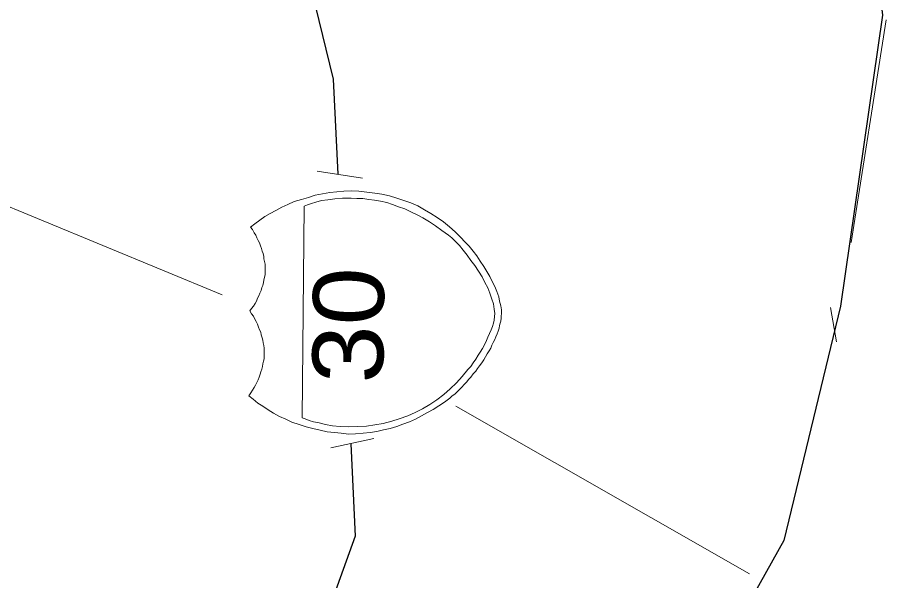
# Model space of a CAD drawing. Extents: x 2356576 to 2377878, y 6966390 to 6990634.
# Drawn here: x 2365920.6 to 2366004.5, y 6968831.6 to 6968885.6 of the extents above; entities that cross this region are included whole.
import ezdxf

# ---------------------------------------------------------------- set-up
doc = ezdxf.new("R2010")
doc.units = 0
doc.header["$LTSCALE"] = 7.1
doc.layers.add('19', color=7, linetype='Continuous', lineweight=13)
doc.layers.add('8', color=7, linetype='Continuous', lineweight=13)

msp = doc.modelspace()

# ---------------------------------------------------------------- linework, layer by layer
at = {"layer": '19'}
for p, q in [((2366003.959, 6968885.355), (2366000.59, 6968864.029)), ((2365949.354, 6968870.86), (2365953.728, 6968870.183)), ((2365999.2, 6968854.503), (2365998.633, 6968857.777)), ((2365962.654, 6968848.341), (2365990.84, 6968832.236)), ((2365950.672, 6968844.325), (2365954.789, 6968845.21))]:
    msp.add_line(p, q, dxfattribs=at)
at = {"layer": '19', "lineweight": 25}
for points in [[(2365993.212, 6969055.404), (2365995.144, 6969044.943), (2365996.174, 6969031.612), (2365997.392, 6969012.874), (2365997.254, 6968999.555), (2365998.323, 6968990.003), (2366002.006, 6968983.305), (2366004.476, 6968969.926), (2366002.874, 6968951.222), (2366001.496, 6968934.107), (2366000.162, 6968915.368), (2366003.604, 6968885.811), (2365999.567, 6968857.919), (2365994.142, 6968835.442), (2365986.716, 6968822.166), (2365969.062, 6968818.241), (2365951.423, 6968818.424), (2365942.698, 6968815.994), (2365930.315, 6968822.751)], [(2365935.418, 6968970.522), (2365940.314, 6968948.062), (2365943.664, 6968909.293), (2365950.886, 6968879.693), (2365951.331, 6968870.568)], [(2365952.596, 6968844.725), (2365953.012, 6968835.868), (2365949.152, 6968825.108), (2365948.988, 6968809.237), (2365953.546, 6968774.267)]]:
    msp.add_lwpolyline(points, dxfattribs=at)
at = {"layer": '19'}
for points in [[(2365898.594, 6968894.279), (2365917.316, 6968868.46), (2365940.231, 6968859.014)], [(2365943.525, 6968858.408), (2365943.648, 6968858.679), (2365943.77, 6968858.917), (2365943.865, 6968859.156), (2365943.988, 6968859.423), (2365944.05, 6968859.694), (2365944.141, 6968859.902), (2365944.203, 6968860.173), (2365944.238, 6968860.413), (2365944.301, 6968860.68), (2365944.363, 6968860.919), (2365944.366, 6968861.191), (2365944.369, 6968861.459), (2365944.371, 6968861.699), (2365944.374, 6968861.939), (2365944.316, 6968862.212), (2365944.259, 6968862.452), (2365944.229, 6968862.693), (2365944.172, 6968862.961), (2365944.087, 6968863.202), (2365944.029, 6968863.443), (2365943.912, 6968863.716), (2365943.823, 6968863.985), (2365943.705, 6968864.226), (2365943.588, 6968864.467), (2365943.47, 6968864.709), (2365943.325, 6968864.95), (2365943.148, 6968865.252), (2365942.97, 6968865.494), (2365943.394, 6968865.822), (2365943.846, 6968866.177), (2365944.329, 6968866.5), (2365944.844, 6968866.795), (2365945.387, 6968867.089), (2365945.958, 6968867.415), (2365946.561, 6968867.677), (2365947.164, 6968867.943), (2365947.858, 6968868.143), (2365948.52, 6968868.349), (2365949.182, 6968868.55), (2365949.872, 6968868.695), (2365950.565, 6968868.807), (2365951.254, 6968868.888), (2365951.915, 6968868.941), (2365952.635, 6968868.966), (2365953.355, 6968868.927), (2365954.134, 6968868.858), (2365954.885, 6968868.763), (2365955.572, 6968868.664), (2365956.29, 6968868.508), (2365957.008, 6968868.261), (2365957.666, 6968868.042), (2365958.355, 6968867.827), (2365959.012, 6968867.52), (2365959.668, 6968867.153), (2365960.265, 6968866.815), (2365960.889, 6968866.42), (2365961.485, 6968865.994), (2365962.052, 6968865.536), (2365962.615, 6968865.05), (2365963.149, 6968864.505), (2365963.537, 6968864.081), (2365963.953, 6968863.656), (2365964.336, 6968863.204), (2365964.691, 6968862.749), (2365965.018, 6968862.237), (2365965.341, 6968861.722), (2365965.636, 6968861.239), (2365965.931, 6968860.756), (2365966.166, 6968860.273), (2365966.401, 6968859.791), (2365966.608, 6968859.309), (2365966.782, 6968858.799), (2365966.866, 6968858.406), (2365966.982, 6968857.957), (2365967.038, 6968857.564), (2365967.066, 6968857.204)], [(2365967.066, 6968857.204), (2365967.031, 6968856.964), (2365967.029, 6968856.756), (2365966.998, 6968856.485), (2365966.936, 6968856.277), (2365966.874, 6968856.066), (2365966.811, 6968855.798), (2365966.716, 6968855.527), (2365966.626, 6968855.26), (2365966.503, 6968854.99), (2365966.408, 6968854.723), (2365966.257, 6968854.424), (2365966.135, 6968854.185), (2365966.011, 6968853.887), (2365965.857, 6968853.616), (2365965.674, 6968853.35), (2365965.523, 6968853.052), (2365965.34, 6968852.782), (2365965.157, 6968852.483), (2365964.942, 6968852.186), (2365964.759, 6968851.947), (2365964.576, 6968851.681), (2365964.334, 6968851.412), (2365964.123, 6968851.114), (2365963.908, 6968850.908), (2365963.698, 6968850.638), (2365963.483, 6968850.401), (2365963.24, 6968850.135), (2365963.03, 6968849.925), (2365962.788, 6968849.688), (2365962.574, 6968849.482), (2365962.332, 6968849.304), (2365962.09, 6968849.095), (2365961.578, 6968848.712), (2365961.034, 6968848.358), (2365960.49, 6968848.003), (2365959.947, 6968847.709), (2365959.372, 6968847.383), (2365958.801, 6968847.089), (2365958.226, 6968846.827), (2365957.595, 6968846.593), (2365957.021, 6968846.387), (2365956.359, 6968846.186), (2365955.73, 6968846.041), (2365955.096, 6968845.899), (2365954.435, 6968845.786), (2365953.774, 6968845.733), (2365953.054, 6968845.68), (2365952.393, 6968845.655), (2365951.674, 6968845.723), (2365951.015, 6968845.79), (2365950.327, 6968845.857), (2365949.637, 6968846.016), (2365948.951, 6968846.171), (2365948.292, 6968846.358), (2365947.635, 6968846.577), (2365946.945, 6968846.792), (2365946.348, 6968847.07), (2365945.751, 6968847.344), (2365945.186, 6968847.65), (2365944.649, 6968847.988), (2365944.141, 6968848.321), (2365943.664, 6968848.626), (2365943.219, 6968848.99), (2365942.803, 6968849.327), (2365942.986, 6968849.593), (2365943.169, 6968849.863), (2365943.319, 6968850.129), (2365943.441, 6968850.34), (2365943.564, 6968850.607), (2365943.687, 6968850.846), (2365943.782, 6968851.117), (2365943.904, 6968851.383), (2365943.967, 6968851.623), (2365944.057, 6968851.862), (2365944.12, 6968852.133), (2365944.155, 6968852.373), (2365944.217, 6968852.64), (2365944.28, 6968852.88), (2365944.282, 6968853.12), (2365944.285, 6968853.42), (2365944.288, 6968853.632), (2365944.29, 6968853.9), (2365944.233, 6968854.14), (2365944.176, 6968854.413), (2365944.146, 6968854.653), (2365944.089, 6968854.894), (2365944.003, 6968855.163), (2365943.946, 6968855.435), (2365943.828, 6968855.645), (2365943.739, 6968855.917), (2365943.622, 6968856.187), (2365943.505, 6968856.46), (2365943.387, 6968856.669), (2365943.242, 6968856.943), (2365943.064, 6968857.185), (2365942.887, 6968857.454), (2365943.07, 6968857.692), (2365943.252, 6968857.903), (2365943.403, 6968858.169), (2365943.525, 6968858.408)]]:
    msp.add_lwpolyline(points, dxfattribs=at)
msp.add_lwpolyline([(2365948.12, 6968867.513), (2365947.909, 6968847.202), (2365948.208, 6968847.111), (2365948.599, 6968846.955), (2365949.017, 6968846.83), (2365949.556, 6968846.737), (2365950.155, 6968846.578), (2365950.842, 6968846.451), (2365951.561, 6968846.384), (2365952.401, 6968846.347), (2365953.213, 6968846.367), (2365954.081, 6968846.418), (2365954.895, 6968846.529), (2365955.704, 6968846.673), (2365956.518, 6968846.873), (2365957.241, 6968847.105), (2365958.052, 6968847.397), (2365958.775, 6968847.721), (2365959.471, 6968848.074), (2365960.163, 6968848.487), (2365960.86, 6968848.928), (2365961.525, 6968849.433), (2365962.131, 6968849.995), (2365962.737, 6968850.56), (2365963.283, 6968851.183), (2365963.83, 6968851.837), (2365964.101, 6968852.134), (2365964.317, 6968852.492), (2365964.588, 6968852.821), (2365964.804, 6968853.207), (2365965.015, 6968853.505), (2365965.231, 6968853.863), (2365965.415, 6968854.221), (2365965.599, 6968854.611), (2365965.75, 6968854.937), (2365965.906, 6968855.296), (2365966.058, 6968855.654), (2365966.181, 6968855.953), (2365966.276, 6968856.284), (2365966.339, 6968856.583), (2365966.371, 6968856.911), (2365966.406, 6968857.211), (2365966.35, 6968857.631), (2365966.296, 6968858.144), (2365966.12, 6968858.594), (2365965.946, 6968859.168), (2365965.739, 6968859.678), (2365965.445, 6968860.193), (2365965.182, 6968860.736), (2365964.856, 6968861.279), (2365964.502, 6968861.823), (2365964.119, 6968862.307), (2365963.764, 6968862.79), (2365963.377, 6968863.274), (2365963.021, 6968863.726), (2365962.665, 6968864.09), (2365962.281, 6968864.454), (2365961.952, 6968864.729), (2365961.328, 6968865.184), (2365960.733, 6968865.61), (2365960.137, 6968866.008), (2365959.508, 6968866.375), (2365958.944, 6968866.681), (2365958.346, 6968866.955), (2365957.777, 6968867.233), (2365957.179, 6968867.447), (2365956.582, 6968867.665), (2365956.044, 6968867.851), (2365955.445, 6968867.977), (2365954.878, 6968868.071), (2365954.306, 6968868.137), (2365953.739, 6968868.235), (2365953.167, 6968868.24), (2365952.628, 6968868.274), (2365951.787, 6968868.255), (2365951.067, 6968868.202), (2365950.378, 6968868.117), (2365949.777, 6968868.036), (2365949.236, 6968867.889), (2365948.814, 6968867.746), (2365948.421, 6968867.63)], close=True, dxfattribs=at)
at = {"layer": '8'}
for p, q in [((2366003.959, 6968885.355), (2366000.59, 6968864.029)), ((2365949.354, 6968870.86), (2365953.728, 6968870.183)), ((2365999.2, 6968854.503), (2365998.633, 6968857.777)), ((2365962.654, 6968848.341), (2365990.84, 6968832.236)), ((2365950.672, 6968844.325), (2365954.789, 6968845.21))]:
    msp.add_line(p, q, dxfattribs=at)
at = {"layer": '8', "lineweight": 25}
for points in [[(2365993.212, 6969055.404), (2365995.144, 6969044.943), (2365996.174, 6969031.612), (2365997.392, 6969012.874), (2365997.254, 6968999.555), (2365998.323, 6968990.003), (2366002.006, 6968983.305), (2366004.476, 6968969.926), (2366002.874, 6968951.222), (2366001.496, 6968934.107), (2366000.162, 6968915.368), (2366003.604, 6968885.811), (2365999.567, 6968857.919), (2365994.142, 6968835.442), (2365986.716, 6968822.166), (2365969.062, 6968818.241), (2365951.423, 6968818.424), (2365942.698, 6968815.994), (2365930.315, 6968822.751)], [(2365935.418, 6968970.522), (2365940.314, 6968948.062), (2365943.664, 6968909.293), (2365950.886, 6968879.693), (2365951.331, 6968870.568)], [(2365952.596, 6968844.725), (2365953.012, 6968835.868), (2365949.152, 6968825.108), (2365948.988, 6968809.237), (2365953.546, 6968774.267)]]:
    msp.add_lwpolyline(points, dxfattribs=at)
at = {"layer": '8'}
for points in [[(2365898.594, 6968894.279), (2365917.316, 6968868.46), (2365940.231, 6968859.014)], [(2365943.525, 6968858.408), (2365943.648, 6968858.679), (2365943.77, 6968858.917), (2365943.865, 6968859.156), (2365943.988, 6968859.423), (2365944.05, 6968859.694), (2365944.141, 6968859.902), (2365944.203, 6968860.173), (2365944.238, 6968860.413), (2365944.301, 6968860.68), (2365944.363, 6968860.919), (2365944.366, 6968861.191), (2365944.369, 6968861.459), (2365944.371, 6968861.699), (2365944.374, 6968861.939), (2365944.316, 6968862.212), (2365944.259, 6968862.452), (2365944.229, 6968862.693), (2365944.172, 6968862.961), (2365944.087, 6968863.202), (2365944.029, 6968863.443), (2365943.912, 6968863.716), (2365943.823, 6968863.985), (2365943.705, 6968864.226), (2365943.588, 6968864.467), (2365943.47, 6968864.709), (2365943.325, 6968864.95), (2365943.148, 6968865.252), (2365942.97, 6968865.494), (2365943.394, 6968865.822), (2365943.846, 6968866.177), (2365944.329, 6968866.5), (2365944.844, 6968866.795), (2365945.387, 6968867.089), (2365945.958, 6968867.415), (2365946.561, 6968867.677), (2365947.164, 6968867.943), (2365947.858, 6968868.143), (2365948.52, 6968868.349), (2365949.182, 6968868.55), (2365949.872, 6968868.695), (2365950.565, 6968868.807), (2365951.254, 6968868.888), (2365951.915, 6968868.941), (2365952.635, 6968868.966), (2365953.355, 6968868.927), (2365954.134, 6968868.858), (2365954.885, 6968868.763), (2365955.572, 6968868.664), (2365956.29, 6968868.508), (2365957.008, 6968868.261), (2365957.666, 6968868.042), (2365958.355, 6968867.827), (2365959.012, 6968867.52), (2365959.668, 6968867.153), (2365960.265, 6968866.815), (2365960.889, 6968866.42), (2365961.485, 6968865.994), (2365962.052, 6968865.536), (2365962.615, 6968865.05), (2365963.149, 6968864.505), (2365963.537, 6968864.081), (2365963.953, 6968863.656), (2365964.336, 6968863.204), (2365964.691, 6968862.749), (2365965.018, 6968862.237), (2365965.341, 6968861.722), (2365965.636, 6968861.239), (2365965.931, 6968860.756), (2365966.166, 6968860.273), (2365966.401, 6968859.791), (2365966.608, 6968859.309), (2365966.782, 6968858.799), (2365966.866, 6968858.406), (2365966.982, 6968857.957), (2365967.038, 6968857.564), (2365967.066, 6968857.204)], [(2365967.066, 6968857.204), (2365967.031, 6968856.964), (2365967.029, 6968856.756), (2365966.998, 6968856.485), (2365966.936, 6968856.277), (2365966.874, 6968856.066), (2365966.811, 6968855.798), (2365966.716, 6968855.527), (2365966.626, 6968855.26), (2365966.503, 6968854.99), (2365966.408, 6968854.723), (2365966.257, 6968854.424), (2365966.135, 6968854.185), (2365966.011, 6968853.887), (2365965.857, 6968853.616), (2365965.674, 6968853.35), (2365965.523, 6968853.052), (2365965.34, 6968852.782), (2365965.157, 6968852.483), (2365964.942, 6968852.186), (2365964.759, 6968851.947), (2365964.576, 6968851.681), (2365964.334, 6968851.412), (2365964.123, 6968851.114), (2365963.908, 6968850.908), (2365963.698, 6968850.638), (2365963.483, 6968850.401), (2365963.24, 6968850.135), (2365963.03, 6968849.925), (2365962.788, 6968849.688), (2365962.574, 6968849.482), (2365962.332, 6968849.304), (2365962.09, 6968849.095), (2365961.578, 6968848.712), (2365961.034, 6968848.358), (2365960.49, 6968848.003), (2365959.947, 6968847.709), (2365959.372, 6968847.383), (2365958.801, 6968847.089), (2365958.226, 6968846.827), (2365957.595, 6968846.593), (2365957.021, 6968846.387), (2365956.359, 6968846.186), (2365955.73, 6968846.041), (2365955.096, 6968845.899), (2365954.435, 6968845.786), (2365953.774, 6968845.733), (2365953.054, 6968845.68), (2365952.393, 6968845.655), (2365951.674, 6968845.723), (2365951.015, 6968845.79), (2365950.327, 6968845.857), (2365949.637, 6968846.016), (2365948.951, 6968846.171), (2365948.292, 6968846.358), (2365947.635, 6968846.577), (2365946.945, 6968846.792), (2365946.348, 6968847.07), (2365945.751, 6968847.344), (2365945.186, 6968847.65), (2365944.649, 6968847.988), (2365944.141, 6968848.321), (2365943.664, 6968848.626), (2365943.219, 6968848.99), (2365942.803, 6968849.327), (2365942.986, 6968849.593), (2365943.169, 6968849.863), (2365943.319, 6968850.129), (2365943.441, 6968850.34), (2365943.564, 6968850.607), (2365943.687, 6968850.846), (2365943.782, 6968851.117), (2365943.904, 6968851.383), (2365943.967, 6968851.623), (2365944.057, 6968851.862), (2365944.12, 6968852.133), (2365944.155, 6968852.373), (2365944.217, 6968852.64), (2365944.28, 6968852.88), (2365944.282, 6968853.12), (2365944.285, 6968853.42), (2365944.288, 6968853.632), (2365944.29, 6968853.9), (2365944.233, 6968854.14), (2365944.176, 6968854.413), (2365944.146, 6968854.653), (2365944.089, 6968854.894), (2365944.003, 6968855.163), (2365943.946, 6968855.435), (2365943.828, 6968855.645), (2365943.739, 6968855.917), (2365943.622, 6968856.187), (2365943.505, 6968856.46), (2365943.387, 6968856.669), (2365943.242, 6968856.943), (2365943.064, 6968857.185), (2365942.887, 6968857.454), (2365943.07, 6968857.692), (2365943.252, 6968857.903), (2365943.403, 6968858.169), (2365943.525, 6968858.408)]]:
    msp.add_lwpolyline(points, dxfattribs=at)
msp.add_lwpolyline([(2365948.12, 6968867.513), (2365947.909, 6968847.202), (2365948.208, 6968847.111), (2365948.599, 6968846.955), (2365949.017, 6968846.83), (2365949.556, 6968846.737), (2365950.155, 6968846.578), (2365950.842, 6968846.451), (2365951.561, 6968846.384), (2365952.401, 6968846.347), (2365953.213, 6968846.367), (2365954.081, 6968846.418), (2365954.895, 6968846.529), (2365955.704, 6968846.673), (2365956.518, 6968846.873), (2365957.241, 6968847.105), (2365958.052, 6968847.397), (2365958.775, 6968847.721), (2365959.471, 6968848.074), (2365960.163, 6968848.487), (2365960.86, 6968848.928), (2365961.525, 6968849.433), (2365962.131, 6968849.995), (2365962.737, 6968850.56), (2365963.283, 6968851.183), (2365963.83, 6968851.837), (2365964.101, 6968852.134), (2365964.317, 6968852.492), (2365964.588, 6968852.821), (2365964.804, 6968853.207), (2365965.015, 6968853.505), (2365965.231, 6968853.863), (2365965.415, 6968854.221), (2365965.599, 6968854.611), (2365965.75, 6968854.937), (2365965.906, 6968855.296), (2365966.058, 6968855.654), (2365966.181, 6968855.953), (2365966.276, 6968856.284), (2365966.339, 6968856.583), (2365966.371, 6968856.911), (2365966.406, 6968857.211), (2365966.35, 6968857.631), (2365966.296, 6968858.144), (2365966.12, 6968858.594), (2365965.946, 6968859.168), (2365965.739, 6968859.678), (2365965.445, 6968860.193), (2365965.182, 6968860.736), (2365964.856, 6968861.279), (2365964.502, 6968861.823), (2365964.119, 6968862.307), (2365963.764, 6968862.79), (2365963.377, 6968863.274), (2365963.021, 6968863.726), (2365962.665, 6968864.09), (2365962.281, 6968864.454), (2365961.952, 6968864.729), (2365961.328, 6968865.184), (2365960.733, 6968865.61), (2365960.137, 6968866.008), (2365959.508, 6968866.375), (2365958.944, 6968866.681), (2365958.346, 6968866.955), (2365957.777, 6968867.233), (2365957.179, 6968867.447), (2365956.582, 6968867.665), (2365956.044, 6968867.851), (2365955.445, 6968867.977), (2365954.878, 6968868.071), (2365954.306, 6968868.137), (2365953.739, 6968868.235), (2365953.167, 6968868.24), (2365952.628, 6968868.274), (2365951.787, 6968868.255), (2365951.067, 6968868.202), (2365950.378, 6968868.117), (2365949.777, 6968868.036), (2365949.236, 6968867.889), (2365948.814, 6968867.746), (2365948.421, 6968867.63)], close=True, dxfattribs=at)

# ---------------------------------------------------------------- texts
at = {"layer": '19', "width": 1.1}
msp.add_text('30', height=6.798, rotation=89.406, dxfattribs=at).set_placement((2365955.684, 6968850.481))
at = {"layer": '8', "width": 1.1}
msp.add_text('30', height=6.798, rotation=89.406, dxfattribs=at).set_placement((2365955.684, 6968850.481))

doc.saveas('drawing.dxf')
